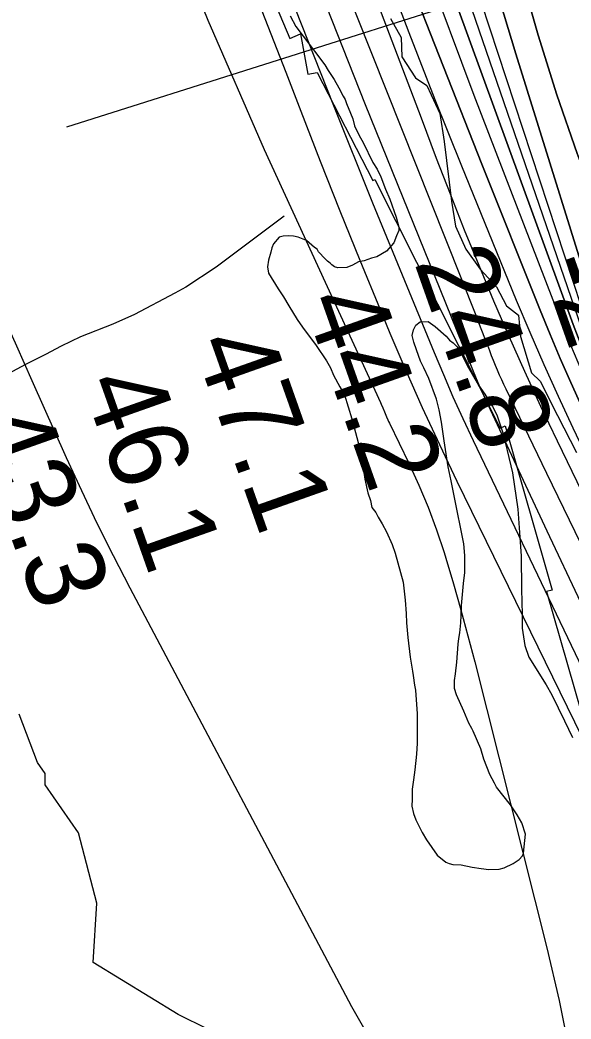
# Model space of a CAD drawing. Extents: x 3177185 to 3215018, y 812988 to 838321.
# Drawn here: x 3197169 to 3197636, y 819169 to 820017 of the extents above; entities that cross this region are included whole.
import ezdxf

# ---------------------------------------------------------------- set-up
doc = ezdxf.new("R2010")
doc.units = 0
for name, color, linetype in [('V-RIVR-EDGE', 7, 'Continuous'), ('V-RIVR-RANG', 7, 'Continuous'), ('V-RRAP-RVMT', 7, 'Continuous'), ('V-SITE-VEGE', 7, 'Continuous'), ('V-TOPO-DPTH', 7, 'Continuous'), ('V-TOPO-MAJR', 7, 'Continuous'), ('V-TOPO-MINR', 7, 'Continuous'), ('V-TOPO-SHOR', 7, 'Continuous'), ('V-TOPO-WATR', 7, 'Continuous')]:
    doc.layers.add(name, color=color, linetype=linetype)

msp = doc.modelspace()

# ---------------------------------------------------------------- linework, layer by layer
at = {"layer": 'V-RIVR-EDGE'}
for points in [[(3197482.93, 820017.88), (3197492.01, 820001.77), (3197492.41, 819985.25)], [(3197492.41, 819985.25), (3197504.1, 819967.4), (3197513.65, 819960.86), (3197524.89, 819937.36), (3197528.31, 819913.44), (3197534.7, 819863), (3197538.13, 819841.69), (3197546.77, 819822.11), (3197558.9, 819805.13), (3197572.78, 819790.32), (3197581.43, 819774.21), (3197591.41, 819766.36), (3197593.1, 819748.1), (3197602.59, 819717.22), (3197609.96, 819710.24), (3197624.67, 819681.08), (3197640.67, 819649.75)]]:
    msp.add_lwpolyline(points, dxfattribs=at)
at = {"layer": 'V-RIVR-RANG'}
msp.add_line((3197208.46, 819925.79), (3197995.79, 820175.56), dxfattribs=at)
at = {"layer": 'V-RRAP-RVMT'}
for p, q in [((3197361.42, 820086.34), (3197397.68, 820000.88)), ((3197397.68, 820000.88), (3197406.68, 820004.81)), ((3197406.68, 820004.81), (3197412.84, 819970.57)), ((3197412.84, 819970.57), (3197420.63, 819971.99)), ((3197420.63, 819971.99), (3197467.9, 819880.36)), ((3197467.9, 819880.36), (3197469.62, 819881.24)), ((3197469.62, 819881.24), (3197575.86, 819670.45)), ((3197575.86, 819670.45), (3197580.19, 819672.52)), ((3197580.19, 819672.52), (3197619.91, 819533.11)), ((3197619.91, 819533.11), (3197615.2, 819531.88)), ((3197615.2, 819531.88), (3197644.81, 819428.67))]:
    msp.add_line(p, q, dxfattribs=at)
at = {"layer": 'V-SITE-VEGE'}
for p, q in [((3197397.71, 820019.94), (3197402.64, 820011.09)), ((3197402.64, 820011.09), (3197408.79, 820002.66)), ((3197408.79, 820002.66), (3197427.2, 819978.58)), ((3197427.2, 819978.58), (3197430.08, 819973.75)), ((3197430.08, 819973.75), (3197435, 819966.12)), ((3197435, 819966.12), (3197439.11, 819958.88)), ((3197439.11, 819958.88), (3197442.82, 819952.05)), ((3197442.82, 819952.05), (3197444.46, 819949.23)), ((3197444.46, 819949.23), (3197445.71, 819945.6)), ((3197445.71, 819945.6), (3197449.02, 819937.55)), ((3197449.02, 819937.55), (3197451.08, 819932.72)), ((3197451.08, 819932.72), (3197452.35, 819926.67)), ((3197452.35, 819926.67), (3197456.47, 819918.62)), ((3197456.47, 819918.62), (3197459.76, 819912.59)), ((3197459.76, 819912.59), (3197468.01, 819895.69)), ((3197468.01, 819895.69), (3197471.7, 819890.06)), ((3197471.7, 819890.06), (3197474.59, 819883.62)), ((3197474.59, 819883.62), (3197478.73, 819873.15)), ((3197478.73, 819873.15), (3197482.45, 819864.7)), ((3197482.45, 819864.7), (3197487.85, 819849.39)), ((3197487.85, 819849.39), (3197489.95, 819840.92)), ((3197489.98, 819838.09), (3197488, 819833.62)), ((3197489.95, 819840.92), (3197489.98, 819838.09)), ((3197388.56, 819832.28), (3197383.77, 819826.57)), ((3197391.79, 819833.12), (3197388.56, 819832.28)), ((3197396.64, 819833.56), (3197391.79, 819833.12)), ((3197400.68, 819833.2), (3197396.64, 819833.56)), ((3197404.73, 819832.43), (3197400.68, 819833.2)), ((3197411.63, 819829.67), (3197404.73, 819832.43)), ((3197418.56, 819823.67), (3197411.63, 819829.67)), ((3197485.63, 819827.53), (3197479.63, 819820.6)), ((3197488, 819833.62), (3197485.63, 819827.53)), ((3197381.41, 819819.68), (3197379.45, 819812.79)), ((3197382.18, 819823.32), (3197381.41, 819819.68)), ((3197383.77, 819826.57), (3197382.18, 819823.32)), ((3197420.6, 819822.07), (3197418.56, 819823.67)), ((3197421.83, 819820.06), (3197420.6, 819822.07)), ((3197427.55, 819814.05), (3197421.83, 819820.06)), ((3197479.63, 819820.6), (3197471.19, 819815.67)), ((3197379.45, 819812.79), (3197378.7, 819807.12)), ((3197429.59, 819812.05), (3197427.55, 819814.05)), ((3197431.62, 819810.45), (3197429.59, 819812.05)), ((3197433.26, 819808.85), (3197431.62, 819810.45)), ((3197455.87, 819811.49), (3197450.64, 819808.61)), ((3197460.71, 819812.34), (3197455.87, 819811.49)), ((3197466.76, 819814.42), (3197460.71, 819812.34)), ((3197471.19, 819815.67), (3197466.76, 819814.42)), ((3197378.7, 819807.12), (3197379.55, 819801.87)), ((3197379.55, 819801.87), (3197387.77, 819788.61)), ((3197435.29, 819807.25), (3197433.26, 819808.85)), ((3197438.13, 819806.47), (3197435.29, 819807.25)), ((3197445.81, 819806.54), (3197438.13, 819806.47)), ((3197450.64, 819808.61), (3197445.81, 819806.54)), ((3197387.77, 819788.61), (3197392.27, 819781.78)), ((3197392.27, 819781.78), (3197396.8, 819774.14)), ((3197396.8, 819774.14), (3197403.78, 819762.48)), ((3197403.78, 819762.48), (3197408.29, 819756.06)), ((3197504.48, 819757.78), (3197508.1, 819760.64)), ((3197508.1, 819760.64), (3197514.97, 819760.71)), ((3197514.97, 819760.71), (3197520.66, 819756.71)), ((3197408.29, 819756.06), (3197419.75, 819740.4)), ((3197501.33, 819748.85), (3197502.5, 819753.71)), ((3197502.5, 819753.71), (3197504.48, 819757.78)), ((3197520.66, 819756.71), (3197530.04, 819748.32)), ((3197502.6, 819743.21), (3197501.33, 819748.85)), ((3197505.09, 819736.76), (3197502.6, 819743.21)), ((3197530.04, 819748.32), (3197532.9, 819745.11)), ((3197532.9, 819745.11), (3197536.16, 819742.71)), ((3197536.16, 819742.71), (3197539.42, 819739.51)), ((3197419.75, 819740.4), (3197428.77, 819727.55)), ((3197508.41, 819727.09), (3197505.09, 819736.76)), ((3197539.42, 819739.51), (3197543.12, 819733.08)), ((3197428.77, 819727.55), (3197432.06, 819721.52)), ((3197511.3, 819721.46), (3197508.41, 819727.09)), ((3197543.12, 819733.08), (3197548.06, 819723.42)), ((3197432.06, 819721.52), (3197434.54, 819715.48)), ((3197515.42, 819712.6), (3197511.3, 819721.46)), ((3197548.06, 819723.42), (3197557.52, 819706.94)), ((3197434.54, 819715.48), (3197439.89, 819705.42)), ((3197522.06, 819694.88), (3197515.42, 819712.6)), ((3197439.89, 819705.42), (3197444, 819698.59)), ((3197557.52, 819706.94), (3197562.85, 819699.31)), ((3197444, 819698.59), (3197450.25, 819678.43)), ((3197524.16, 819686), (3197522.06, 819694.88)), ((3197562.85, 819699.31), (3197569.41, 819688.86)), ((3197526.28, 819675.51), (3197524.16, 819686)), ((3197569.41, 819688.86), (3197573.12, 819681.61)), ((3197450.25, 819678.43), (3197457.39, 819651.01)), ((3197528.45, 819659.77), (3197526.28, 819675.51)), ((3197573.12, 819681.61), (3197578.53, 819665.49)), ((3197531.9, 819637.57), (3197528.45, 819659.77)), ((3197578.53, 819665.49), (3197584.85, 819638.47)), ((3197457.39, 819651.01), (3197459.04, 819647.39)), ((3197459.04, 819647.39), (3197458.66, 819644.15)), ((3197458.66, 819644.15), (3197459.96, 819634.86)), ((3197459.96, 819634.86), (3197461.25, 819627.2)), ((3197534.43, 819625.87), (3197531.9, 819637.57)), ((3197584.85, 819638.47), (3197586.52, 819632.42)), ((3197586.52, 819632.42), (3197590.85, 819601.74)), ((3197461.25, 819627.2), (3197463.78, 819615.49)), ((3197539.96, 819597.62), (3197534.43, 819625.87)), ((3197463.78, 819615.49), (3197465.87, 819609.05)), ((3197465.87, 819609.05), (3197467.14, 819603)), ((3197467.14, 819603), (3197470.41, 819598.98)), ((3197470.41, 819598.98), (3197472.47, 819594.96)), ((3197590.85, 819601.74), (3197592.25, 819581.94)), ((3197472.47, 819594.96), (3197475.76, 819589.33)), ((3197542.07, 819587.94), (3197539.96, 819597.62)), ((3197475.76, 819589.33), (3197479.46, 819582.5)), ((3197479.46, 819582.5), (3197484.41, 819571.63)), ((3197545.04, 819572.2), (3197542.07, 819587.94)), ((3197592.25, 819581.94), (3197593.66, 819561.74)), ((3197484.41, 819571.63), (3197486.91, 819564.37)), ((3197545.95, 819562.51), (3197545.04, 819572.2)), ((3197486.91, 819564.37), (3197493.61, 819539.78)), ((3197546.08, 819547.95), (3197545.95, 819562.51)), ((3197593.66, 819561.74), (3197593.92, 819533.85)), ((3197544.96, 819538.64), (3197546.08, 819547.95)), ((3197493.61, 819539.78), (3197495.37, 819524.43)), ((3197543.12, 819520.03), (3197544.96, 819538.64)), ((3197593.92, 819533.85), (3197594.53, 819512.44)), ((3197495.37, 819524.43), (3197496.29, 819513.12)), ((3197542.79, 819511.54), (3197543.12, 819520.03)), ((3197496.29, 819513.12), (3197496.36, 819505.44)), ((3197496.36, 819505.44), (3197497.69, 819492.92)), ((3197541.71, 819496.98), (3197542.44, 819505.47)), ((3197542.44, 819505.47), (3197542.79, 819511.54)), ((3197594.53, 819512.44), (3197594.64, 819500.71)), ((3197540.95, 819492.12), (3197541.71, 819496.98)), ((3197594.64, 819500.71), (3197596.8, 819486.18)), ((3197497.69, 819492.92), (3197499.46, 819476.36)), ((3197540.19, 819487.26), (3197540.95, 819492.12)), ((3197539.12, 819471.89), (3197540.19, 819487.26)), ((3197596.8, 819486.18), (3197600.12, 819476.1)), ((3197499.46, 819476.36), (3197501.6, 819464.26)), ((3197538, 819462.18), (3197539.12, 819471.89)), ((3197600.12, 819476.1), (3197614.9, 819452.79)), ((3197501.6, 819464.26), (3197502.04, 819460.62)), ((3197502.04, 819460.62), (3197503.33, 819452.55)), ((3197537.25, 819456.51), (3197538, 819462.18)), ((3197537.31, 819449.64), (3197537.25, 819456.51)), ((3197503.33, 819452.55), (3197504.18, 819448.11)), ((3197504.18, 819448.11), (3197505.58, 819428.31)), ((3197538.98, 819444.4), (3197537.31, 819449.64)), ((3197614.9, 819452.79), (3197619.83, 819444.35)), ((3197545.18, 819430.3), (3197538.98, 819444.4)), ((3197619.83, 819444.35), (3197630.55, 819422.22)), ((3197549.31, 819420.24), (3197545.18, 819430.3)), ((3197183.63, 819386.96), (3197167.93, 819427.8)), ((3197505.58, 819428.31), (3197505.41, 819403.25)), ((3197630.55, 819422.22), (3197637.15, 819408.13)), ((3197551.78, 819415.82), (3197549.31, 819420.24)), ((3197553.02, 819413.4), (3197551.78, 819415.82)), ((3197559.62, 819398.51), (3197553.02, 819413.4)), ((3197505.41, 819403.25), (3197505.09, 819393.95)), ((3197562.14, 819389.64), (3197559.62, 819398.51)), ((3197189.91, 819377.54), (3197183.63, 819386.96)), ((3197505.09, 819393.95), (3197503.6, 819380.59)), ((3197567.11, 819376.75), (3197562.14, 819389.64)), ((3197503.6, 819380.59), (3197502.47, 819372.09)), ((3197189.91, 819368.11), (3197189.91, 819377.54)), ((3197502.47, 819372.09), (3197501.33, 819364.4)), ((3197571.22, 819369.51), (3197567.11, 819376.75)), ((3197218.17, 819327.28), (3197189.91, 819368.11)), ((3197501.33, 819364.4), (3197501.41, 819355.91)), ((3197572.87, 819365.89), (3197571.22, 819369.51)), ((3197584.73, 819351.04), (3197572.87, 819365.89)), ((3197501.41, 819355.91), (3197501.06, 819349.84)), ((3197501.06, 819349.84), (3197502.33, 819343.79)), ((3197590.47, 819342.61), (3197584.73, 819351.04)), ((3197502.33, 819343.79), (3197504.41, 819338.15)), ((3197504.41, 819338.15), (3197509.76, 819327.69)), ((3197594.18, 819335.77), (3197590.47, 819342.61)), ((3197597.5, 819326.1), (3197594.18, 819335.77)), ((3197233.86, 819267.59), (3197218.17, 819327.28)), ((3197509.76, 819327.69), (3197513.46, 819321.26)), ((3197513.46, 819321.26), (3197522.48, 819308.41)), ((3197595.63, 819309.91), (3197597.5, 819326.1)), ((3197522.48, 819308.41), (3197529.81, 819302.42)), ((3197529.81, 819302.42), (3197532.65, 819301.23)), ((3197586.82, 819301.34), (3197592.04, 819304.62)), ((3197592.04, 819304.62), (3197594.84, 819307.88)), ((3197594.84, 819307.88), (3197595.63, 819309.91)), ((3197532.65, 819301.23), (3197535.89, 819300.45)), ((3197535.89, 819300.45), (3197542.77, 819300.11)), ((3197542.77, 819300.11), (3197552.09, 819298.18)), ((3197552.09, 819298.18), (3197559.78, 819297.04)), ((3197559.78, 819297.04), (3197566.25, 819296.29)), ((3197566.25, 819296.29), (3197575.14, 819296.37)), ((3197575.14, 819296.37), (3197579.18, 819297.62)), ((3197579.18, 819297.62), (3197586.82, 819301.34)), ((3197230.72, 819217.33), (3197233.86, 819267.59)), ((3197302.93, 819173.35), (3197230.72, 819217.33)), ((3197328.05, 819160.79), (3197302.93, 819173.35))]:
    msp.add_line(p, q, dxfattribs=at)
at = {"layer": 'V-TOPO-DPTH'}
for points in [[(3198031.77, 819158.23), (3197984.16, 819231.2), (3197939.59, 819306.07), (3197897.04, 819382.2), (3197730.37, 819695.43), (3197715.03, 819725.47), (3197700.39, 819755.83), (3197686.8, 819786.66), (3197673.89, 819817.82), (3197659.78, 819853.6), (3197641.23, 819903.17), (3197623.85, 819953.14), (3197608.24, 820003.68), (3197593.82, 820054.61), (3197385.39, 820842.97)], [(3197385.39, 820842.97), (3197593.82, 820054.61), (3197608.24, 820003.68), (3197623.85, 819953.14), (3197641.23, 819903.17), (3197659.78, 819853.6), (3197673.89, 819817.82), (3197686.8, 819786.66), (3197700.39, 819755.83), (3197715.03, 819725.47), (3197730.37, 819695.43), (3197897.04, 819382.2), (3197939.59, 819306.07), (3197984.16, 819231.2), (3198031.77, 819158.23)], [(3197195.81, 820818.87), (3197244.5, 820654.03), (3197273.63, 820560.07), (3197304.42, 820466.68), (3197337.72, 820374.15), (3197372.67, 820282.2), (3197435.58, 820123.17), (3197454.17, 820075.86), (3197472.61, 820028.49), (3197490.83, 819981.04), (3197508.9, 819933.53), (3197521.77, 819899.43), (3197533.48, 819869), (3197545.43, 819838.67), (3197557.74, 819808.48), (3197570.3, 819778.39), (3197583.27, 819748.48), (3197596.52, 819718.69), (3197610.22, 819689.11), (3197624.2, 819659.66), (3198029.73, 818821.68)], [(3197962.83, 819088.03), (3197905.07, 819193.56), (3197849.22, 819300.05), (3197796.25, 819408), (3197745.2, 819516.93), (3197655.64, 819714.92), (3197650.93, 819725.64), (3197646.4, 819736.42), (3197642.1, 819747.3), (3197637.97, 819758.24), (3197538.67, 820030.59), (3197490.29, 820167.23), (3197443.61, 820304.44), (3197399.5, 820442.49), (3197357.1, 820581.11), (3197285.44, 820823.43)], [(3197285.44, 820823.43), (3197357.1, 820581.11), (3197399.5, 820442.49), (3197443.61, 820304.44), (3197490.29, 820167.23), (3197538.67, 820030.59), (3197637.97, 819758.24), (3197642.1, 819747.3), (3197646.4, 819736.42), (3197650.93, 819725.64), (3197655.64, 819714.92), (3197745.2, 819516.93), (3197796.25, 819408), (3197849.22, 819300.05), (3197905.07, 819193.56), (3197962.83, 819088.03)], [(3197991.7, 819162.41), (3197948.67, 819235.62), (3197808.68, 819476.5), (3197788.13, 819512.2), (3197767.78, 819548.01), (3197747.73, 819583.98), (3197727.87, 819620.07), (3197701.8, 819667.93), (3197695.26, 819680.24), (3197688.91, 819692.64), (3197682.83, 819705.17), (3197676.94, 819717.79), (3197666.56, 819740.63), (3197666.01, 819741.91), (3197664.58, 819745.84), (3197589.13, 819987.8), (3197552.26, 820110.46), (3197517.07, 820233.58), (3197484.4, 820357.4), (3197453.41, 820481.67), (3197371.82, 820823.76)], [(3197371.82, 820823.76), (3197453.41, 820481.67), (3197484.4, 820357.4), (3197517.07, 820233.58), (3197552.26, 820110.46), (3197589.13, 819987.8), (3197664.58, 819745.84), (3197666.01, 819741.91), (3197666.56, 819740.63), (3197676.94, 819717.79), (3197682.83, 819705.17), (3197688.91, 819692.64), (3197695.26, 819680.24), (3197701.8, 819667.93), (3197727.87, 819620.07), (3197747.73, 819583.98), (3197767.78, 819548.01), (3197788.13, 819512.2), (3197808.68, 819476.5), (3197948.67, 819235.62), (3197991.7, 819162.41)], [(3197352.02, 820672.38), (3197371.15, 820609.01), (3197390.99, 820545.85), (3197411.32, 820482.84), (3197651.61, 819752.16), (3197653.75, 819745.97), (3197656.03, 819739.84), (3197658.51, 819733.79), (3197661.12, 819727.78), (3197709.76, 819620.68), (3197737.49, 819561.52), (3197766.17, 819502.83), (3197796.24, 819444.84), (3197827.26, 819387.33), (3198034.41, 819014.08)], [(3197352.02, 820672.38), (3197371.15, 820609.01), (3197390.99, 820545.85), (3197411.32, 820482.84), (3197651.61, 819752.16), (3197653.75, 819745.97), (3197656.03, 819739.84), (3197658.51, 819733.79), (3197661.12, 819727.78), (3197709.76, 819620.68), (3197737.49, 819561.52), (3197766.17, 819502.83), (3197796.24, 819444.84), (3197827.26, 819387.33), (3198034.41, 819014.08)], [(3197899.93, 819145.11), (3197861.14, 819225.85), (3197645.02, 819689.03), (3197635.82, 819709.2), (3197626.85, 819729.47), (3197618.23, 819749.89), (3197609.84, 819770.42), (3197560.46, 819894.28), (3197527.81, 819976.9), (3197495.49, 820059.66), (3197463.67, 820142.6), (3197432.18, 820225.68), (3197318.81, 820527.48), (3197305.83, 820561.81), (3197292.75, 820596.1), (3197279.51, 820630.33), (3197266.18, 820664.53)], [(3197899.93, 819145.11), (3197861.14, 819225.85), (3197645.02, 819689.03), (3197635.82, 819709.2), (3197626.85, 819729.47), (3197618.23, 819749.89), (3197609.84, 819770.42), (3197560.46, 819894.28), (3197527.81, 819976.9), (3197495.49, 820059.66), (3197463.67, 820142.6), (3197432.18, 820225.68), (3197318.81, 820527.48), (3197305.83, 820561.81), (3197292.75, 820596.1), (3197279.51, 820630.33), (3197266.18, 820664.53)]]:
    msp.add_lwpolyline(points, dxfattribs=at)
at = {"layer": 'V-TOPO-MAJR'}
msp.add_lwpolyline([(3197169.42, 820662.33), (3197339.43, 820193.69), (3197370.31, 820110.2), (3197401.88, 820026.96), (3197434.48, 819944.13), (3197467.77, 819861.56), (3197519.87, 819734.61), (3197527.79, 819715.79), (3197535.92, 819697.07), (3197544.37, 819678.49), (3197553.04, 819660.01), (3197671.61, 819412.71), (3197729.11, 819294.29), (3197787.4, 819176.27), (3197846.87, 819058.84), (3197907.13, 818941.8), (3198007.95, 818748.35), (3198018.49, 818728.39), (3198029.19, 818708.51), (3198040.12, 818688.76), (3198051.2, 818669.08), (3198170.24, 818460.43), (3198223.54, 818367.96), (3198228.2, 818359.98)], dxfattribs=at)
at = {"layer": 'V-TOPO-MINR'}
for points in [[(3197293.16, 820836.09), (3197346.23, 820654.15), (3197377.16, 820550.87), (3197409.08, 820447.9), (3197442.47, 820345.4), (3197476.85, 820243.21), (3197644.9, 819755.24), (3197647.99, 819746.66), (3197651.24, 819738.14), (3197654.74, 819729.72), (3197658.39, 819721.36), (3197726.54, 819571.19), (3197765.43, 819488.32), (3197805.71, 819406.15), (3197848.06, 819325.03), (3197891.8, 819244.61), (3198154.57, 818775.85)], [(3197385.39, 820842.97), (3197593.82, 820054.61), (3197608.24, 820003.68), (3197623.85, 819953.14), (3197641.23, 819903.17), (3197659.78, 819853.6), (3197673.89, 819817.82), (3197686.8, 819786.66), (3197700.39, 819755.83), (3197715.03, 819725.47), (3197730.37, 819695.43), (3197897.04, 819382.2), (3197939.59, 819306.07), (3197984.16, 819231.2), (3198031.77, 819158.23)], [(3197195.81, 820818.87), (3197244.5, 820654.03), (3197273.63, 820560.07), (3197304.42, 820466.68), (3197337.72, 820374.15), (3197372.67, 820282.2), (3197435.58, 820123.17), (3197454.17, 820075.86), (3197472.61, 820028.49), (3197490.83, 819981.04), (3197508.9, 819933.53), (3197521.77, 819899.43), (3197533.48, 819869), (3197545.43, 819838.67), (3197557.74, 819808.48), (3197570.3, 819778.39), (3197583.27, 819748.48), (3197596.52, 819718.69), (3197610.22, 819689.11), (3197624.2, 819659.66), (3198029.73, 818821.68)], [(3197285.44, 820823.43), (3197357.1, 820581.11), (3197399.5, 820442.49), (3197443.61, 820304.44), (3197490.29, 820167.23), (3197538.67, 820030.59), (3197637.97, 819758.24), (3197642.1, 819747.3), (3197646.4, 819736.42), (3197650.93, 819725.64), (3197655.64, 819714.92), (3197745.2, 819516.93), (3197796.25, 819408), (3197849.22, 819300.05), (3197905.07, 819193.56), (3197962.83, 819088.03)], [(3197371.82, 820823.76), (3197453.41, 820481.67), (3197484.4, 820357.4), (3197517.07, 820233.58), (3197552.26, 820110.46), (3197589.13, 819987.8), (3197664.58, 819745.84), (3197666.01, 819741.91), (3197666.56, 819740.63), (3197676.94, 819717.79), (3197682.83, 819705.17), (3197688.91, 819692.64), (3197695.26, 819680.24), (3197701.8, 819667.93), (3197727.87, 819620.07), (3197747.73, 819583.98), (3197767.78, 819548.01), (3197788.13, 819512.2), (3197808.68, 819476.5), (3197948.67, 819235.62), (3197991.7, 819162.41)], [(3197277.79, 820810.78), (3197401.73, 820396.89), (3197436.71, 820284.8), (3197473.4, 820173.3), (3197512.67, 820062.68), (3197553.64, 819952.65), (3197626.76, 819763.05), (3197632.6, 819748.31), (3197638.61, 819733.65), (3197644.89, 819719.1), (3197651.35, 819704.62), (3197787.76, 819406.19), (3197839.85, 819296), (3197893.8, 819186.76), (3197950.54, 819078.95), (3198009.15, 818972.08), (3198113.19, 818788), (3198121.27, 818773.95), (3198129.5, 818759.98), (3198137.92, 818746.14), (3198146.49, 818732.38), (3198382.49, 818359.62)], [(3197101.67, 820805.66), (3197148.44, 820639.25), (3197175.94, 820547.4), (3197205.48, 820456.26), (3197238.09, 820366.16), (3197272.74, 820276.77), (3197301.38, 820206.46), (3197324.96, 820148.05), (3197348.31, 820089.55), (3197371.3, 820030.91), (3197394.07, 819972.17), (3197406.77, 819939.1), (3197423.18, 819896.9), (3197439.84, 819854.8), (3197456.85, 819812.85), (3197474.11, 819770.99), (3197482.46, 819750.98), (3197496, 819719.33), (3197509.91, 819687.84), (3197524.39, 819656.61), (3197539.23, 819625.55), (3197844.87, 819000.56)], [(3197172.15, 820777.18), (3197284.37, 820430.79), (3197325.56, 820308.2), (3197368.49, 820186.24), (3197414.05, 820065.24), (3197461.36, 819944.88), (3197552.51, 819720.11), (3197555.61, 819712.63), (3197558.79, 819705.19), (3197562.08, 819697.79), (3197565.45, 819690.43), (3197615.39, 819583.45), (3197644.13, 819522.79), (3197673.32, 819462.35), (3197703.2, 819402.24), (3197733.53, 819342.36), (3198044.81, 818736.38), (3198049.01, 818728.36), (3198053.3, 818720.39), (3198057.73, 818712.5), (3198062.25, 818704.66), (3198264.61, 818359.89)], [(3197233.54, 820721.83), (3197252.48, 820660.72), (3197272.48, 820599.98), (3197294.08, 820539.78), (3197316.74, 820479.95), (3197326.88, 820454.24), (3197355.24, 820381.76), (3197383.39, 820309.2), (3197411.21, 820236.51), (3197438.81, 820163.74), (3197476.93, 820062.53), (3197498.59, 820005.8), (3197520.59, 819949.2), (3197543.11, 819892.8), (3197565.96, 819836.53), (3197589.61, 819779.05), (3197601.11, 819751.72), (3197612.9, 819724.52), (3197625.13, 819697.51), (3197637.65, 819670.64), (3197941.36, 819032.03)], [(3197352.02, 820672.38), (3197371.15, 820609.01), (3197390.99, 820545.85), (3197411.32, 820482.84), (3197651.61, 819752.16), (3197653.75, 819745.97), (3197656.03, 819739.84), (3197658.51, 819733.79), (3197661.12, 819727.78), (3197709.76, 819620.68), (3197737.49, 819561.52), (3197766.17, 819502.83), (3197796.24, 819444.84), (3197827.26, 819387.33), (3198034.41, 819014.08)], [(3197283.16, 820127.33), (3197327.95, 820016.5), (3197375.73, 819906.81), (3197474.37, 819692.24), (3197475.07, 819690.69), (3197476.41, 819687.56), (3197477.77, 819684.19), (3197479.48, 819680.07), (3197480.67, 819677.34), (3197481.3, 819675.99), (3197481.94, 819674.64), (3197498.53, 819640.62), (3197507.04, 819622.09), (3197514.94, 819603.33), (3197521.95, 819584.21), (3197528.36, 819564.86), (3197529.78, 819560.22), (3197536.29, 819538.33), (3197542.58, 819516.38), (3197548.56, 819494.34), (3197554.32, 819472.25), (3197615.62, 819229.86), (3197625.9, 819185.09), (3197634.88, 819140.08)], [(3197428.77, 820084.51), (3197555.17, 819766.23), (3197557.68, 819759.88), (3197560.16, 819753.51), (3197562.62, 819747.14), (3197565.05, 819740.76), (3197566.74, 819736.31), (3197568.34, 819732.16), (3197569.98, 819728.02), (3197571.68, 819723.91), (3197573.41, 819719.81), (3197575.19, 819715.74), (3197577.01, 819711.68), (3197578.88, 819707.64), (3197580.79, 819703.62), (3197615.13, 819632.29), (3197634.3, 819592.65), (3197653.56, 819553.06), (3197672.95, 819513.53), (3197692.43, 819474.04), (3198060.37, 818731.31)], [(3197474.58, 819136.87), (3197450.04, 819179.62), (3197262.07, 819534.74), (3197247.95, 819562.08), (3197234.2, 819589.6), (3197221, 819617.4), (3197208.18, 819645.37), (3197179.11, 819710.51), (3197165.9, 819740.03), (3197152.65, 819769.53), (3197139.32, 819798.99), (3197125.95, 819828.44), (3197099.15, 819887.31)]]:
    msp.add_lwpolyline(points, dxfattribs=at)
at = {"layer": 'V-TOPO-SHOR'}
msp.add_lwpolyline([(3197392.69, 819850.05), (3197335.03, 819806.94), (3197309.45, 819789.87), (3197299.93, 819784.83), (3197265.79, 819766.69), (3197247.39, 819758.6), (3197220.11, 819747.79), (3197203.68, 819740.04), (3197190.23, 819732.98), (3197173.48, 819724.25), (3197158.71, 819716.52)], dxfattribs=at)
at = {"layer": 'V-TOPO-WATR'}
msp.add_lwpolyline([(3197266.18, 820664.53), (3197279.51, 820630.33), (3197292.75, 820596.1), (3197305.83, 820561.81), (3197318.81, 820527.48), (3197432.18, 820225.68), (3197463.67, 820142.6), (3197495.49, 820059.66), (3197527.81, 819976.9), (3197560.46, 819894.28), (3197609.84, 819770.42), (3197618.23, 819749.89), (3197626.85, 819729.47), (3197635.82, 819709.2), (3197645.02, 819689.03), (3197861.14, 819225.85), (3197899.93, 819145.11)], dxfattribs=at)

# ---------------------------------------------------------------- texts
at = {"layer": 'V-RIVR-RANG'}
for s, rotation, p in [('24.8', 289.47833, (3197502.68, 819811.27)), ('-24', 289.55075, (3197609.29, 819809.46)), ('44.2', 289.47833, (3197408.49, 819777.7)), ('47.1', 289.47833, (3197315.09, 819741.89)), ('46.1', 289.47833, (3197220.89, 819708.32)), ('43.3', 289.47833, (3197125.9, 819676.98))]:
    msp.add_text(s, height=67, rotation=rotation, dxfattribs=at).set_placement(p)

doc.saveas('drawing.dxf')
